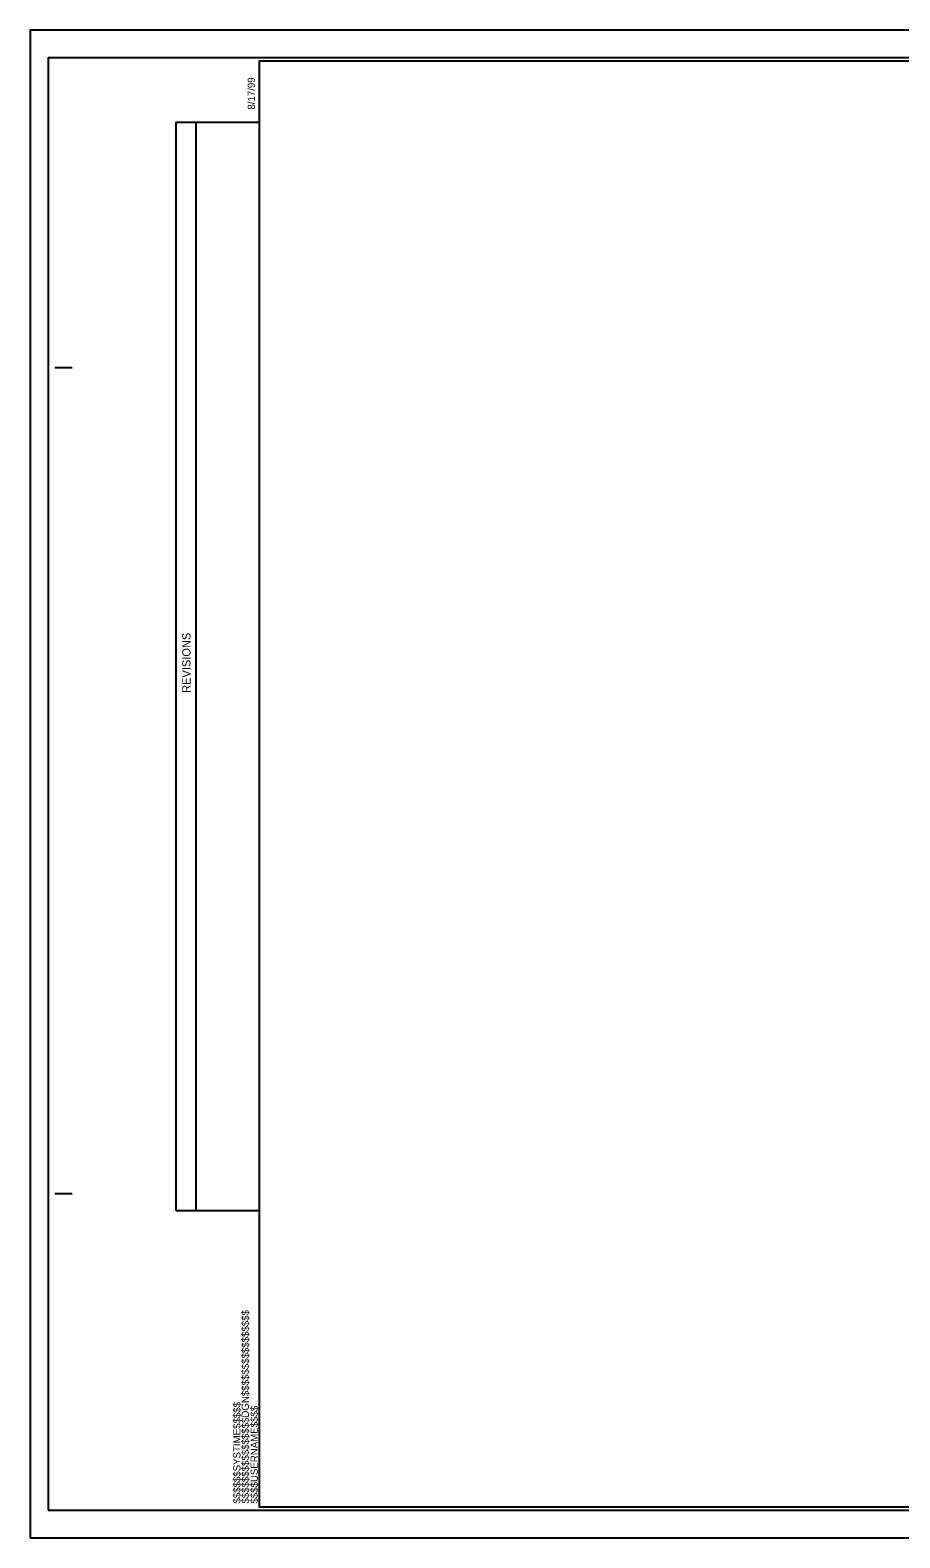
# Model space of a CAD drawing. Extents: x 2530399 to 2530799, y 189629 to 189994.
# Drawn here: x 2530401.6 to 2530464.8, y 189884 to 189993.5 of the extents above; entities that cross this region are included whole.
import ezdxf

# ---------------------------------------------------------------- set-up
doc = ezdxf.new("R2010")
doc.units = 0
for name, color, linetype in [('Sheet Block Revision CELL', 7, 'Continuous'), ('Sheet Cutting Line CELL', 7, 'Continuous'), ('Sheet Plan CELL', 7, 'Continuous'), ('Sheet Plot Border Inside CELL', 7, 'Continuous'), ('Sheet Plot Border Outside CELL', 7, 'Continuous')]:
    doc.layers.add(name, color=color, linetype=linetype)

msp = doc.modelspace()

# ---------------------------------------------------------------- linework, layer by layer
at = {"layer": 'Sheet Block Revision CELL'}
msp.add_line((2530413.64, 189907.76), (2530413.64, 189986.83), dxfattribs=at)
msp.add_lwpolyline([(2530412.19, 189907.76), (2530412.19, 189986.83), (2530418.24, 189986.83), (2530418.24, 189907.76)], close=True, dxfattribs=at)
at = {"layer": 'Sheet Cutting Line CELL'}
for p, q in [((2530569.94, 189993.51), (2530401.59, 189993.51)), ((2530401.59, 189993.51), (2530401.59, 189884.01)), ((2530544.32, 189991.26), (2530423.24, 189991.26)), ((2530423.24, 189886.26), (2530563.24, 189886.26)), ((2530401.59, 189884.01), (2530569.94, 189884.01))]:
    msp.add_line(p, q, dxfattribs=at)
at = {"layer": 'Sheet Plan CELL'}
for p, q in [((2530418.24, 189991.26), (2530418.24, 189991.26)), ((2530403.39, 189969.01), (2530404.64, 189969.01)), ((2530403.39, 189909.01), (2530404.64, 189909.01)), ((2530418.24, 189886.26), (2530418.24, 189886.26))]:
    msp.add_line(p, q, dxfattribs=at)
msp.add_lwpolyline([(2530568.24, 189991.26), (2530418.24, 189991.26), (2530418.24, 189886.26), (2530568.24, 189886.26)], close=True, dxfattribs=at)
at = {"layer": 'Sheet Plot Border Inside CELL'}
msp.add_lwpolyline([(2530402.89, 189886.01), (2530569.49, 189886.01), (2530569.49, 189991.51), (2530402.89, 189991.51)], close=True, dxfattribs=at)
at = {"layer": 'Sheet Plot Border Outside CELL'}
msp.add_lwpolyline([(2530401.59, 189884.01), (2530569.94, 189884.01), (2530569.94, 189993.51), (2530401.59, 189993.51)], close=True, dxfattribs=at)

# ---------------------------------------------------------------- texts
at = {"layer": 'Sheet Block Revision CELL'}
msp.add_text('REVISIONS', height=0.6, rotation=90, dxfattribs=at).set_placement((2530413.24, 189945.38))
at = {"layer": 'Sheet Plan CELL'}
for s, p in [('8/17/99', (2530417.92, 189987.74)), ('$$$$$$$$$$$$$$$$DGN$$$$$$$$$$$$$$$$', (2530417.48, 189886.5)), ('$$$$$$SYSTIME$$$$$', (2530416.87, 189886.5)), ('$$$$USERNAME$$$$', (2530418.13, 189886.5))]:
    msp.add_text(s, height=0.525, rotation=90, dxfattribs=at).set_placement(p)

doc.saveas('drawing.dxf')
